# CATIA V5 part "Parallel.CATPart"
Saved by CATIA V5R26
Part number: Parallel
Bounding box of the stored display mesh (mm): x -379.025 to 257.653, y 0 to 550.967, z -174.504 to 392.31
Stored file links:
  D:\LinkedIn Learning\NURBS\CATIA\Class Parts\Parallel.CATPart
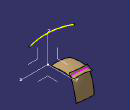
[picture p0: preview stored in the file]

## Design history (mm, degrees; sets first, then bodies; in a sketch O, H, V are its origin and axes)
AxisSystem1: origin (0, 0, 0), X (1, 0, 0), Y (0, 1, 0), Z (0, 0, 1)
Set1
  DatumSurface1
  DatumSurface2
  St3DCurveFeature1 "CATSt3DCurveFeatureName": Order 6, CreationType 1, ClosureMode false, ConstructionPoints ({point type Coord, X 257.6527, Y 0, Z 353.6812}; {point type Coord, X 4.5467, Y 0, Z 447.8526}; {point type Coord, X -379.0254, Y 0, Z 312.4529}), SymmetryMode false
  Intersect1: ToIntersect1 DatumSurface2, ToIntersect2 DatumSurface1
Body1 (main body)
